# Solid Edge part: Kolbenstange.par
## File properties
Username: bmolnar
Dokumentum tartalom típus: 0
Author: bmolnar
Last saved by: bmolnar
Revision: 78
Sűrűség: 0,000 kg/m^3
Pontosság: 0,990
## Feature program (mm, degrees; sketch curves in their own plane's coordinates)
base feature "unnamed BaseFeature 1"
sketch for "unnamed Protrusion 1" plane through (54.2, 0.0012, 0) normal (1, 0, 0) x-axis (0, 0, -1)
  circle centre (0, -0.0012) radius 50
extrude "unnamed Protrusion 1" add finite 21.4 along +normal
sketch for "Kihúzás_2" #1 plane through (54.2, 0.0012, 0) normal (1, 0, 0) x-axis (0, 0, -1)
  circle centre (0, -0.0012) radius 12.5
sketch for "Kihúzás_2" #2 plane through (54.2, 0.0012, 0) normal (1, 0, 0) x-axis (0, 0, -1)
  circle centre (0, -0.0012) radius 50
extrude "Kihúzás_2" add finite 12.85 along -normal
sketch for "Furat_1" plane through (-10, 0.0012, 0) normal (-1, 0, 0) x-axis (0, 0, 1)
  hole centre (0, -0.0012) bore radius 5.053
hole "Furat_1" nominal diameter 12 finite  VBottomAngle = 118 deg; ThreadDepth = 22 mm
chamfer "Letörés_1" setback 1  SetBackValue2 = 45 deg
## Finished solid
Body 1: solid body, 14 faces, 20 edges, 8 vertices.
  Faces by surface: plane 7, cylinder 4, cone 2, torus 1
  Edges by curve: circle 10, line 6, curve on surface 2, ellipse 2
Bounding box of the edges (mm; curved faces can reach further): 85.600 x 100.000 x 100.000, from (-10, -50, -50) to (75.6, 50, 50).
Cylindrical faces by radius (mm): R5.053 x2, R12.5 x1, R50 x1
Conical faces (half-angle, radius in mm at the cone's reference point): 45 deg R6.053 x1, 59 deg R5.053 x1
Toroidal faces (ring radius, tube radius in mm): R10.7 r1.8 x1
Planar faces by outward normal: +x 1, +y 1, -x 2, -y 1, oblique 2
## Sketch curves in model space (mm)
circle centre (54.2, 0, 0) radius 50
circle centre (54.2, 0, 0) radius 12.5
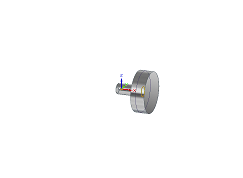
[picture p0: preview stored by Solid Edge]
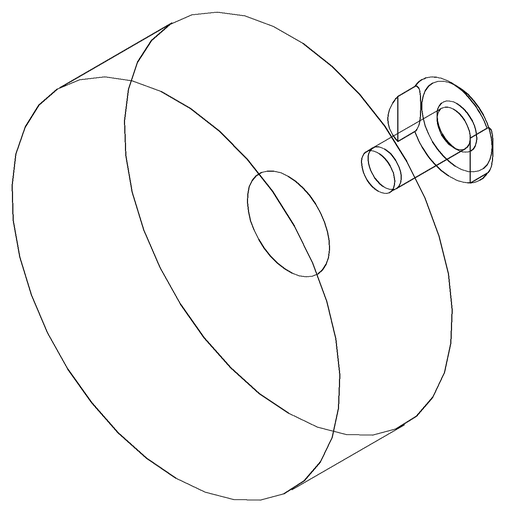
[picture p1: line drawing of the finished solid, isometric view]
